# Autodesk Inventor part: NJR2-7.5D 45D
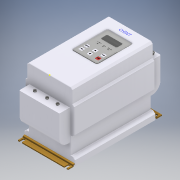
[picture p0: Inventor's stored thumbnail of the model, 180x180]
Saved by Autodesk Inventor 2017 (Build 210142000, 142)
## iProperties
Part Number: NJR2-7.5D 45D
Material: Типовые
Document SubType Name: Modeling
Designer: RSagdiev
Density: 1 g/cm^3
Appearance: По умолчанию
Author: RSagdiev
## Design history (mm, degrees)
sketch "Эскиз1"
  geometry: L1 (0, 0)-(14.471, 0) reference; L2 (0, 0)-(0, 21.118) reference; L3 (0, 0)-(230, 0); L4 (230, 0)-(230, 20); L5 (230, 190)-(0, 190); L6 (0, 190)-(0, 150); L7 (230, 20)-(0, 20); L8 (230, 70)-(0, 70); L9 (230, 70)-(230, 150); L10 (230, 20)-(230, 70); L11 (0, 70)-(0, 20); L12 (0, 20)-(0, 0); L13 (230, 150)-(0, 150); L14 (230, 150)-(230, 190); L15 (0, 150)-(0, 70)
  constraints: 30 end point, 17 parallel, 14 perpendicular, 3 horizontal, 2 vertical, 1 point on line
  dimensions: "d0" = 230 distance of L5.end L5.start; "d1" = 190 distance of L5.start L3.end; "d2" = 20 distance between parallel lines of L3 L7; "d3" = 50 distance between parallel lines of L8 L7; "d4" = 80 distance between parallel lines of L13 L8
extrude "Выдавливание1" new body sketch "Эскиз1" stored distance "d5" = 145; taper "d6" = 0 deg
extrude "Выдавливание2" join sketch "Эскиз1" stored distance "d7" = 120; taper "d8" = 0 deg
extrude "Выдавливание3" join sketch "Эскиз1" stored distance "d9" = 140; taper "d10" = 0 deg
extrude "Выдавливание4" join sketch "Эскиз1" stored distance "d11" = 130; taper "d12" = 0 deg
chamfer "Фаска1" distance "d13" = 5; stored, may be unused: second distance "d14" = 2, angle "d15" = 45 deg
sketch "Эскиз2"
  geometry: L1 (249, 0)-(234, 0); L2 (233, 1)-(233, 3); L3 (232, 4)-(-2, 4); L4 (-3, 3)-(-3, 1); L5 (-4, 0)-(-19, 0); L6 (230, 15)-(230, 0) reference; L7 (230, 0)-(0, 0) reference; L8 (0, 0)-(0, 15) reference; L9 (249, 3)-(236, 3); L10 (232, 7)-(-2, 7); L11 (-6, 3)-(-19, 3); L12 (-19, 0)-(-19, 3); L13 (249, 3)-(249, 0); A1 r 1 centre (-4, 1) between (-4, 0) and (-3, 1); A2 r 1 centre (-2, 3) between (-2, 4) and (-3, 3); A3 r 1 centre (234, 1) between (233, 1) and (234, 0); A4 r 1 centre (232, 3) between (233, 3) and (232, 4); A5 r 4 centre (232, 3) between (236, 3) and (232, 7); A6 r 4 centre (-2, 3) between (-2, 7) and (-6, 3); 6 further points
  constraints: 20 end point, 12 point on circle, 10 point on line, 8 tangent, 6 centre point, 4 perpendicular, 3 equal radius, 1 horizontal, 1 parallel, 4 other
  dimensions: "d16" = 4 distance of point (233, 0) point (233, 4); "d17" = 3 distance between parallel lines of L2 L6; "d18" = 4 distance between parallel lines of L7 L3; "d19" = 16 distance of point (233, 0) L1.start; "d20" = 16 distance of point (-3, 0) L5.end (= d19); "d21" = 4 distance of point (-3, 4) point (-3, 0) (derived); "d22" = 3 distance between parallel lines of L4 L8 (= d17); "d23" = 268 distance of L5.end L1.start (derived); "d24" = 1 radius of A1; "d25" = 3 distance between parallel lines of L1 L9
extrude "Выдавливание5" new body sketch "Эскиз2" stored distance "d26" = 143; taper "d27" = 0 deg
sketch "Эскиз4"
  geometry: L1 (260, 138)-(-30, 138); L2 (-30, 138)-(-30, 50); L3 (-30, 50)-(260, 50); L4 (260, 50)-(260, 138); L5 (0, 70)-(230, 70) reference; L6 (230, 190)-(230, 150) reference; L7 (230, 0)-(0, 0) reference; L8 (0, 150)-(230, 150) reference
  constraints: 8 end point, 2 parallel, 1 horizontal, 1 perpendicular
  dimensions: "d28" = 290 distance between parallel lines of L2 L4; "d187" = 20 distance between parallel lines of L5 L3; "d188" = 30 distance between parallel lines of L6 L4; "d189" = 50 distance between parallel lines of L7 L3 (derived); "d190" = 12 distance between parallel lines of L8 L1
extrude "Выдавливание6" join sketch "Эскиз4" stored distance "d32" = 115; taper "d33" = 0 deg
fillet "Сопряжение1" dims "d35" = 25
sketch "Эскиз5" dims "d44" = 10
  geometry: L1 (115, 0)-(0, 0) reference; L2 (115, 30)-(115, 0) reference; L3 (115, 30)-(0, 30) reference; L4 (0, 0)-(0, 30) reference; L5 (0, -260)-(115, -260) reference; L6 (0, -230)-(115, -230) reference; L7 (0, -260)-(0, -230) reference; L8 (115, -230)-(115, -260) reference; C1 r 4 at (20, 20); C2 r 4 at (35.833, 20); C3 r 4 at (51.667, 20); C4 r 4 at (67.5, 20); C5 r 4 at (83.333, 20); C6 r 4 at (99.167, 20); 1 further point
  constraints: 6 centre point, 1 horizontal, 10 other
  dimensions: "d36" = 8 diameter of C1; "d37" = 115 distance between parallel lines of L2 L4 (derived); "d38" = 20 distance from line of C1.centre L4; "d41" = 15.83333 distance of C1.centre C2.centre (= -0.166667 x d38 + 0.166667 x d37)
  node "Спроецированная петля1"
extrude "Выдавливание7" cut sketch "Эскиз5" distance "d46" = 20; taper "d47" = 0 deg
extrude "Выдавливание8" new body sketch "Эскиз5" distance "d48" = 20; taper "d49" = 0 deg
sketch "Эскиз6" dims "d50" = 12, "d56" = 10
  geometry: L1 (0, 6)-(5.196, 3); L2 (5.196, 3)-(5.196, -3); L3 (5.196, -3)-(0, -6); L4 (0, -6)-(-5.196, -3); L5 (-5.196, -3)-(-5.196, 3); L6 (-5.196, 3)-(0, 6); L7 (95, 10)-(-20, 10) reference; L8 (15.833, 6)-(21.029, 3); L9 (21.029, 3)-(21.029, -3); L10 (21.029, -3)-(15.833, -6); L11 (15.833, -6)-(10.637, -3); L12 (10.637, -3)-(10.637, 3); L13 (10.637, 3)-(15.833, 6); L14 (31.667, 6)-(36.863, 3); L15 (36.863, 3)-(36.863, -3); L16 (36.863, -3)-(31.667, -6); L17 (31.667, -6)-(26.471, -3); L18 (26.471, -3)-(26.471, 3); L19 (26.471, 3)-(31.667, 6); L20 (47.5, 6)-(52.696, 3); L21 (52.696, 3)-(52.696, -3); L22 (52.696, -3)-(47.5, -6); L23 (47.5, -6)-(42.304, -3); L24 (42.304, -3)-(42.304, 3); L25 (42.304, 3)-(47.5, 6); L26 (63.333, 6)-(68.529, 3); L27 (68.529, 3)-(68.529, -3); L28 (68.529, -3)-(63.333, -6); L29 (63.333, -6)-(58.137, -3); L30 (58.137, -3)-(58.137, 3); L31 (58.137, 3)-(63.333, 6); L32 (79.167, 6)-(84.363, 3); L33 (84.363, 3)-(84.363, -3); L34 (84.363, -3)-(79.167, -6); L35 (79.167, -6)-(73.971, -3); L36 (73.971, -3)-(73.971, 3); L37 (73.971, 3)-(79.167, 6); 13 further points
  constraints: 72 end point, 6 coincident, 6 horizontal, 6 vertical alignment, 95 other
  dimensions: "d53" = 15.83333 distance of point (0, 0) point (15.833, 0) (= -0.166667 x d38 + 0.166667 x d37)
extrude "Выдавливание9" join sketch "Эскиз6" distance "d58" = 5; taper "d59" = 0 deg
sketch "Эскиз7" dims "d185" = 10
  geometry: L1 (2.964, 2.686)-(3.808, -1.224); L2 (3.808, -1.224)-(0.844, -3.91); L3 (0.844, -3.91)-(-2.964, -2.686); L4 (-2.964, -2.686)-(-3.808, 1.224); L5 (-3.808, 1.224)-(-0.844, 3.91); L6 (-0.844, 3.91)-(2.964, 2.686); L7 (95, 10)-(-20, 10) reference; L8 (18.764, 2.686)-(19.608, -1.224); L9 (19.608, -1.224)-(16.644, -3.91); L10 (16.644, -3.91)-(12.836, -2.686); L11 (12.836, -2.686)-(11.992, 1.224); L12 (11.992, 1.224)-(14.956, 3.91); L13 (14.956, 3.91)-(18.764, 2.686); L14 (34.564, 2.686)-(35.408, -1.224); L15 (35.408, -1.224)-(32.444, -3.91); L16 (32.444, -3.91)-(28.636, -2.686); L17 (28.636, -2.686)-(27.792, 1.224); L18 (27.792, 1.224)-(30.756, 3.91); L19 (30.756, 3.91)-(34.564, 2.686); L20 (50.364, 2.686)-(51.208, -1.224); L21 (51.208, -1.224)-(48.244, -3.91); L22 (48.244, -3.91)-(44.436, -2.686); L23 (44.436, -2.686)-(43.592, 1.224); L24 (43.592, 1.224)-(46.556, 3.91); L25 (46.556, 3.91)-(50.364, 2.686); L26 (66.164, 2.686)-(67.008, -1.224); L27 (67.008, -1.224)-(64.044, -3.91); L28 (64.044, -3.91)-(60.236, -2.686); L29 (60.236, -2.686)-(59.392, 1.224); L30 (59.392, 1.224)-(62.356, 3.91); L31 (62.356, 3.91)-(66.164, 2.686); L32 (81.964, 2.686)-(82.808, -1.224); L33 (82.808, -1.224)-(79.844, -3.91); L34 (79.844, -3.91)-(76.036, -2.686); L35 (76.036, -2.686)-(75.192, 1.224); L36 (75.192, 1.224)-(78.156, 3.91); L37 (78.156, 3.91)-(81.964, 2.686); C1 r 6 at (0, 0) reference; A1 r 4 centre (0, 0) between (2.964, 2.686) and (-2.964, -2.686); A2 r 4 centre (15.8, 0) between (18.764, 2.686) and (12.836, -2.686); A3 r 4 centre (31.6, 0) between (34.564, 2.686) and (28.636, -2.686); A4 r 4 centre (47.4, 0) between (50.364, 2.686) and (44.436, -2.686); A5 r 4 centre (63.2, 0) between (66.164, 2.686) and (60.236, -2.686); A6 r 4 centre (79, 0) between (81.964, 2.686) and (76.036, -2.686); 1 further point
  constraints: 72 end point, 36 point on circle, 6 centre point, 5 equal length, 1 horizontal, 70 other
  dimensions: "d179" = 2 radial gap between concentric circles of C1 A1; "d182" = 15.8 distance of L1.start L8.start
extrude "Выдавливание10" cut sketch "Эскиз7" distance "d66" = 1.5; taper "d67" = 0 deg
fillet "Сопряжение2" dims "d68" = 2
sketch "Эскиз8"
  geometry: L1 (0, -268)-(143, -268) reference; L2 (143, 0)-(0, 0) reference; L3 (143, 0)-(143, -15) reference; L4 (0, -15)-(0, 0) reference; L5 (7.5, -9)-(7.5, -14); L6 (135.5, -9)-(135.5, -14); L7 (7.5, -9)-(135.5, -9); L8 (7.5, -259)-(7.5, -268); L9 (4, -259)-(4, -268); L10 (11, -268)-(11, -259); L11 (7.5, -9)-(7.5, -259); L12 (7.5, -259)-(135.5, -259); L13 (135.5, -9)-(135.5, -259); L14 (135.5, -259)-(135.5, -268); L15 (132, -259)-(132, -268); L16 (139, -268)-(139, -259); A1 r 3.5 centre (7.5, -9) between (10.779, -10.225) and (4.221, -10.225); A2 r 5 centre (7.5, -14) between (4.221, -10.225) and (10.779, -10.225); A3 r 3.5 centre (135.5, -9) between (138.779, -10.225) and (132.221, -10.225); A4 r 5 centre (135.5, -14) between (132.221, -10.225) and (138.779, -10.225); A5 r 3.5 centre (7.5, -259) between (11, -259) and (4, -259); A6 r 3.5 centre (7.5, -268) between (4, -268) and (11, -268); A7 r 3.5 centre (135.5, -259) between (139, -259) and (132, -259); A8 r 3.5 centre (135.5, -268) between (132, -268) and (139, -268); 5 further points
  constraints: 28 end point, 16 point on circle, 8 centre point, 8 tangent, 4 vertical, 3 coincident, 2 horizontal, 2 midpoint, 2 parallel, 2 perpendicular, 2 point on line
  dimensions: "d69" = 128 distance of point (135.5, -9) point (7.5, -9); "d70" = 250 distance of L8.start point (7.5, -9); "d71" = 268 distance between parallel lines of L1 L2 (derived); "d72" = 9 distance from line of L2 point (7.5, -9) (= -0.5 x d70 + 0.5 x d71); "d73" = 143 distance between parallel lines of L3 L4 (derived); "d74" = 7.5 distance from line of L4 point (7.5, -9) (= -0.5 x d69 + 0.5 x d73); "d75" = 7 diameter of A1; "d76" = 10 diameter of A2; "d77" = 5 distance of L5.start L5.end; "d78" = 7 diameter of A3; "d79" = 10 diameter of A4; "d80" = 5 distance of L6.start L6.end; "d81" = 7 diameter of A6; "d82" = 7 diameter of A8
extrude "Выдавливание11" cut sketch "Эскиз8" distance "d83" = 5.5; taper "d84" = 0 deg
fillet "Сопряжение3" dims "d85" = 2
sketch "Эскиз9"
  geometry: L1 (125, 0)-(5, 0); L2 (5, 226)-(125, 226); L3 (33, 193)-(97, 193); L4 (100, 190)-(100, 96); L5 (97, 93)-(33, 93); L6 (30, 96)-(30, 190); L7 (97, 195)-(33, 195); L8 (28, 190)-(28, 96); L9 (33, 91)-(97, 91); L10 (102, 96)-(102, 190); L11 (125, 226)-(125, 0); L12 (5, 0)-(5, 226); A1 r 3 centre (33, 190) between (33, 193) and (30, 190); A2 r 3 centre (97, 190) between (100, 190) and (97, 193); A3 r 3 centre (97, 96) between (97, 93) and (100, 96); A4 r 3 centre (33, 96) between (30, 96) and (33, 93); A5 r 5 centre (33, 190) between (33, 195) and (28, 190); A6 r 5 centre (33, 96) between (28, 96) and (33, 91); A7 r 5 centre (97, 96) between (97, 91) and (102, 96); A8 r 5 centre (97, 190) between (102, 190) and (97, 195); 4 further points
  constraints: 24 end point, 16 point on circle, 8 centre point, 8 tangent, 6 point on line, 4 parallel, 3 equal radius, 2 perpendicular, 1 horizontal, 7 other
  dimensions: "d86" = 70 distance of point (100, 93) point (30, 93); "d87" = 100 distance of point (100, 193) point (100, 93); "d90" = 33 distance between parallel lines of L2 L3 (computed from d89, d87); "d92" = 3 radius of A1; "d93" = 2 distance between parallel lines of L3 L7
extrude "Выдавливание12" cut sketch "Эскиз9" distance "d94" = 25; taper "d95" = 0 deg
extrude "Выдавливание13" new body sketch "Эскиз9" distance "d96" = 25; taper "d97" = 0 deg
sketch "Эскиз10"
  geometry: L1 (30, 190)-(30, 150.574); L2 (33, 93)-(97, 93); L3 (100, 96)-(100, 150.574); L4 (97, 193)-(33, 193); L5 (97, 193)-(33, 193) reference; L6 (30, 190)-(30, 96) reference; L7 (30, 150.574)-(30, 96); L8 (100, 150.574)-(100, 190); L9 (45.628, 161.287)-(84.628, 161.287); L10 (87.628, 164.287)-(87.628, 176.287); L11 (84.628, 179.287)-(45.628, 179.287); L12 (42.628, 176.287)-(42.628, 164.287); L13 (42.628, 161.287)-(87.628, 179.287); L14 (87.628, 161.287)-(42.628, 179.287); A1 r 3 centre (33, 96) between (30, 96) and (33, 93); A2 r 3 centre (97, 96) between (97, 93) and (100, 96); A3 r 3 centre (97, 190) between (100, 190) and (97, 193); A4 r 3 centre (33, 190) between (33, 193) and (30, 190); A5 r 55 centre (65, 193) between (30, 150.574) and (100.197, 150.737); A6 r 3 centre (45.628, 176.287) between (45.628, 179.287) and (42.628, 176.287); A7 r 3 centre (45.628, 164.287) between (42.628, 164.287) and (45.628, 161.287); A8 r 3 centre (84.628, 176.287) between (87.628, 176.287) and (84.628, 179.287); A9 r 3 centre (84.628, 164.287) between (84.628, 161.287) and (87.628, 164.287); 2 further points
  constraints: 20 end point, 11 point on circle, 9 centre point, 9 point on line, 8 tangent, 3 equal radius, 3 midpoint, 2 parallel, 1 horizontal, 1 perpendicular
  dimensions: "d98" = 55 radius of A5; "d99" = 45 distance of L14.end L13.end; "d100" = 18 distance of L13.end L14.start; "d101" = 22.7132 distance from line of L4 point (65.128, 170.287); "d102" = 35.1281 distance from line of L1 point (65.128, 170.287); "d103" = 3 radius of A6 (derived)
extrude "Выдавливание14" cut sketch "Эскиз10" distance "d104" = 1; taper "d105" = 0 deg
sketch "Эскиз11"
  geometry: L1 (30, 150.574)-(30, 96) reference; L2 (33, 93)-(97, 93) reference; L3 (100, 96)-(100, 150.574) reference; L4 (30, 150.574)-(30, 96) reference; L5 (30, 123)-(100, 123); L6 (100, 96)-(100, 150.574) reference; L7 (30, 108)-(100, 108); L8 (33, 93)-(97, 93) reference; L9 (41.667, 93)-(41.667, 143.195); L10 (88.333, 93)-(88.333, 143.195); L11 (65, 93)-(65, 138); L12 (36.667, 128)-(46.667, 128); L13 (46.667, 128)-(46.667, 118); L14 (46.667, 118)-(36.667, 118); L15 (36.667, 118)-(36.667, 128); L16 (36.667, 128)-(46.667, 118); L17 (46.667, 128)-(36.667, 118); L18 (36.667, 113)-(46.667, 113); L19 (46.667, 113)-(46.667, 103); L20 (46.667, 103)-(36.667, 103); L21 (36.667, 103)-(36.667, 113); L22 (36.667, 113)-(46.667, 103); L23 (46.667, 113)-(36.667, 103); L24 (60, 128)-(70, 128); L25 (70, 128)-(70, 118); L26 (70, 118)-(60, 118); L27 (60, 118)-(60, 128); L28 (60, 128)-(70, 118); L29 (70, 128)-(60, 118); L30 (60, 113)-(70, 113); L31 (70, 113)-(70, 103); L32 (70, 103)-(60, 103); L33 (60, 103)-(60, 113); L34 (60, 113)-(70, 103); L35 (70, 113)-(60, 103); L36 (83.333, 128)-(93.333, 128); L37 (93.333, 128)-(93.333, 118); L38 (93.333, 118)-(83.333, 118); L39 (83.333, 118)-(83.333, 128); L40 (83.333, 128)-(93.333, 118); L41 (93.333, 128)-(83.333, 118); L42 (83.333, 113)-(93.333, 113); L43 (93.333, 113)-(93.333, 103); L44 (93.333, 103)-(83.333, 103); L45 (83.333, 103)-(83.333, 113); L46 (83.333, 113)-(93.333, 103); L47 (93.333, 113)-(83.333, 103); L48 (46.767, 128.1)-(36.567, 128.1); L49 (36.567, 128.1)-(36.567, 117.9); L50 (36.567, 117.9)-(46.767, 117.9); L51 (46.767, 117.9)-(46.767, 128.1); L52 (70.1, 128.1)-(59.9, 128.1); L53 (59.9, 128.1)-(59.9, 117.9); L54 (59.9, 117.9)-(70.1, 117.9); L55 (70.1, 117.9)-(70.1, 128.1); L56 (93.433, 128.1)-(83.233, 128.1); L57 (83.233, 128.1)-(83.233, 117.9); L58 (83.233, 117.9)-(93.433, 117.9); L59 (93.433, 117.9)-(93.433, 128.1); L60 (46.767, 113.1)-(36.567, 113.1); L61 (36.567, 113.1)-(36.567, 102.9); L62 (36.567, 102.9)-(46.767, 102.9); L63 (46.767, 102.9)-(46.767, 113.1); L64 (70.1, 113.1)-(59.9, 113.1)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; A1 r 55 centre (65, 193) between (30, 150.574) and (100, 150.574) reference; A2 r 3 centre (33, 96) between (30, 96) and (33, 93) reference; A3 r 3 centre (97, 96) between (97, 93) and (100, 96) reference; A4 r 55 centre (65, 193) between (30, 150.574) and (100, 150.574) reference; 8 further points
  constraints: 130 end point, 24 parallel, 16 midpoint, 16 point on line, 14 perpendicular, 7 horizontal, 4 point on circle, 1 vertical, 18 other
  dimensions: "d106" = 70 distance between parallel lines of L3 L1 (derived); "d107" = 45 distance from line of L2 L11.end (derived); "d108" = 15 distance between parallel lines of L7 L5 (= 0.333333 x d107); "d109" = 15 distance from line of L11.end L5 (= 0.333333 x d107); "d110" = 23.33333 distance between parallel lines of L11 L10 (= 0.333333 x d106); "d111" = 23.33333 distance between parallel lines of L11 L9 (= d110); "d112" = 10 distance of L13.end L14.end; "d113" = 10 distance of L12.end L13.end; "d114" = 10 distance of L19.end L20.end; "d115" = 10 distance of L18.end L19.end; "d116" = 10 distance of L25.end L26.end; "d117" = 10 distance of L24.end L25.end; "d118" = 10 distance of L31.end L32.end; "d119" = 10 distance of L30.end L31.end; "d120" = 10 distance of L37.end L38.end; "d121" = 10 distance of L36.end L37.end; "d122" = 10 distance of L43.end L44.end; "d123" = 10 distance of L42.end L43.end; "d124" = 0.1 distance between parallel lines of L12 L48; "d125" = 0.1 distance between parallel lines of L24 L52; "d126" = 0.1 distance between parallel lines of L36 L56; "d127" = 0.1 distance between parallel lines of L18 L60; "d128" = 0.1 distance between parallel lines of L30 L64; "d129" = 0.1 distance between parallel lines of L42 L68
extrude "Выдавливание15" cut sketch "Эскиз11" distance "d130" = 3; taper "d131" = 0 deg
sketch "Эскиз12"
  geometry: L1 (100, 96)-(100, 150.574) reference; L2 (50, 144.701)-(80, 144.701); C1 r 1.5 at (65, 144.701); C2 r 1.5 at (80, 144.701); C3 r 1.5 at (50, 144.701); C4 r 1.6 at (50, 144.701); C5 r 1.6 at (65, 144.701); C6 r 1.6 at (80, 144.701); A1 r 55 centre (65, 193) between (30, 150.574) and (100, 150.574) reference; 1 further point
  constraints: 6 centre point, 2 end point, 1 coincident, 1 horizontal, 1 midpoint
  dimensions: "d132" = 3 diameter of C1; "d133" = 3 diameter of C2; "d134" = 3 diameter of C3; "d135" = 48.29941 distance of A1.centre C1.centre; "d136" = 35 distance from line of L1 C1.centre; "d137" = 15 distance of C1.centre C2.centre; "d138" = 15 distance of C1.centre L2.start; "d139" = 0.1 radial gap between concentric circles of C3 C4; "d140" = 0.1 radial gap between concentric circles of C1 C5; "d141" = 0.1 radial gap between concentric circles of C2 C6
extrude "Выдавливание16" cut sketch "Эскиз12" distance "d142" = 3; taper "d143" = 0 deg
sketch "Эскиз13"
  geometry: L1 (45, 150.348)-(102.075, 150.348); L2 (102.075, 150.348)-(102.075, 146.701); L3 (102.075, 146.701)-(45, 146.701); L4 (45, 146.701)-(45, 150.348); C1 r 1.5 at (50, 144.701) reference; 1 further point
  constraints: 2 other
  dimensions: "d144" = 2 vertical distance of L3.end C1.centre; "d145" = 5 horizontal distance of C1.centre L3.end
feature "Рельеф1" sketch "Эскиз13" dims "d10" = 0, "d146" = 0.1, "d147" = 0
sketch "Эскиз14"
  geometry: L1 (36.734, 124.406)-(51.145, 124.406); L2 (51.145, 124.406)-(51.145, 120.906); L3 (51.145, 120.906)-(36.734, 120.906); L4 (36.734, 120.906)-(36.734, 124.406); L5 (38.873, 106.059)-(38.873, 109.559); L6 (38.873, 109.559)-(53.285, 109.559); L7 (53.285, 109.559)-(53.285, 106.059); L8 (53.285, 106.059)-(38.873, 106.059); L9 (84.699, 105.985)-(84.699, 109.485); L10 (84.699, 109.485)-(99.11, 109.485); L11 (99.11, 109.485)-(99.11, 105.985); L12 (99.11, 105.985)-(84.699, 105.985); L13 (85.21, 120.906)-(85.21, 124.406); L14 (85.21, 124.406)-(99.621, 124.406); L15 (99.621, 124.406)-(99.621, 120.906); L16 (99.621, 120.906)-(85.21, 120.906); 1 further point
  constraints: 8 other
feature "Рельеф2" dims "d10" = 0, "d148" = 0.1, "d149" = 0
feature "Рельеф3" dims "d10" = 0, "d150" = 0.1, "d151" = 0
feature "Рельеф4" dims "d10" = 0, "d152" = 0.1, "d153" = 0
feature "Рельеф5" dims "d10" = 0, "d154" = 0.1, "d155" = 0
sketch "Эскиз15" dims "d156" = 6, "d157" = 6
  geometry: L1 (60, 128)-(60, 118) reference; L2 (60, 118)-(70, 118) reference; L3 (70, 118)-(70, 128) reference; L4 (70, 128)-(60, 128) reference; L5 (60, 113)-(60, 103) reference; L6 (60, 103)-(70, 103) reference; L7 (70, 103)-(70, 113) reference; L8 (70, 113)-(60, 113) reference; L9 (60, 118)-(70, 128); L10 (60, 128)-(70, 118); L11 (60, 113)-(70, 103); L12 (70.1, 113.1)-(70.1, 102.9) reference; L13 (70.1, 113.1)-(60, 103); L14 (65.05, 126)-(67.573, 121.457); L15 (67.573, 121.457)-(62.377, 121.544); L16 (62.377, 121.544)-(65.05, 126); L17 (65.05, 105.05)-(62.452, 109.55); L18 (62.452, 109.55)-(67.648, 109.55); L19 (67.648, 109.55)-(65.05, 105.05); 5 further points
  constraints: 20 end point, 2 coincident, 2 midpoint, 2 perpendicular, 1 parallel, 1 vertical alignment, 19 other
  node "Спроецированная петля11"
  node "Спроецированная петля12"
feature "Рельеф6" dims "d10" = 0, "d158" = 0.1, "d159" = 0
feature "Рельеф7" dims "d10" = 0, "d160" = 0.1, "d161" = 0
sketch "Эскиз16"
  geometry: L1 (2, -30)-(113, -30) reference; L2 (0, 0)-(115, 0) reference; L3 (90, -10)-(0, -10); L4 (0, -28)-(0, -5) reference; L5 (113, 260)-(2, 260) reference; L6 (115, 230)-(0, 230) reference; L7 (115, 0)-(115, -28) reference; L8 (0, -28)-(0, 0) reference; L9 (0, 230)-(0, 258) reference; L10 (115, 258)-(115, 230) reference; C1 r 4 at (25, -10); C2 r 4 at (60, -10); C3 r 4 at (90, -10); A1 r 2 centre (2, -28) between (0, -28) and (2, -30) reference; A2 r 2 centre (113, -28) between (113, -30) and (115, -28) reference; A3 r 2 centre (113, 258) between (115, 258) and (113, 260) reference; A4 r 2 centre (2, 258) between (2, 260) and (0, 258) reference; 1 further point
  constraints: 3 centre point, 3 point on line, 2 end point, 1 horizontal
  dimensions: "d162" = 8 diameter of C1; "d163" = 8 diameter of C2; "d164" = 8 diameter of C3; "d166" = 20 distance from line of L3.start L1; "d167" = 30 distance of C2.centre L3.start; "d168" = 35 distance of C1.centre C2.centre; "d191" = 25 distance from line of L8 C1.centre
extrude "Выдавливание17" new body sketch "Эскиз16" distance "d169" = 3; taper "d170" = 0 deg
sketch "Эскиз17"
  geometry: L1 (-23, -20)-(88, -20) reference; L2 (-25, 10)-(90, 10) reference; L3 (0, 3)-(2.598, 1.5); L4 (2.598, 1.5)-(2.598, -1.5); L5 (2.598, -1.5)-(0, -3); L6 (0, -3)-(-2.598, -1.5); L7 (-2.598, -1.5)-(-2.598, 1.5); L8 (-2.598, 1.5)-(0, 3); L9 (35, 3)-(37.598, 1.5); L10 (37.598, 1.5)-(37.598, -1.5); L11 (37.598, -1.5)-(35, -3); L12 (35, -3)-(32.402, -1.5); L13 (32.402, -1.5)-(32.402, 1.5); L14 (32.402, 1.5)-(35, 3); L15 (65, 3)-(67.598, 1.5); L16 (67.598, 1.5)-(67.598, -1.5); L17 (67.598, -1.5)-(65, -3); L18 (65, -3)-(62.402, -1.5); L19 (62.402, -1.5)-(62.402, 1.5); L20 (62.402, 1.5)-(65, 3); L21 (88, 270)-(-23, 270) reference; L22 (90, 240)-(-25, 240) reference; L23 (90, 10)-(90, -18) reference; L24 (-25, -18)-(-25, 10) reference; L25 (-25, 240)-(-25, 268) reference; L26 (90, 268)-(90, 240) reference; C1 r 4 at (0, 0) reference; C2 r 4 at (35, 0) reference; C3 r 4 at (65, 0) reference; C4 r 4 at (35, 0) reference; A1 r 2 centre (-23, -18) between (-25, -18) and (-23, -20) reference; A2 r 2 centre (88, -18) between (88, -20) and (90, -18) reference; A3 r 2 centre (88, 268) between (90, 268) and (88, 270) reference; A4 r 2 centre (-23, 268) between (-23, 270) and (-25, 268) reference; 4 further points
  constraints: 36 end point, 3 coincident, 3 vertical alignment, 45 other
  dimensions: "d171" = 1 dimension on C1; "d172" = 1 dimension on C2; "d173" = 1 dimension on C3
extrude "Выдавливание18" cut sketch "Эскиз17" distance "d174" = 0.5; taper "d175" = 0 deg
fillet "Сопряжение4" dims "d176" = 1
sketch "Эскиз18"
  geometry: L1 (46.683, 214.728)-(62.561, 214.728); L2 (62.561, 214.728)-(62.561, 211.091); L3 (62.561, 211.091)-(46.683, 211.091); L4 (46.683, 211.091)-(46.683, 214.728); 1 further point
  constraints: 2 other
feature "Рельеф8" sketch "Эскиз18" dims "d10" = 0, "d177" = 0.1, "d178" = 0
node "Твердое тело1"
node "Твердое тело2"
node "Твердое тело3"
node "Твердое тело4"
node "Спроецированная петля10"
node "Спроецированная петля13"
node "Твердое тело5"
node "Спроецированная петля14"
node "Спроецированная петля15"
node "Спроецированная петля16"
node "Спроецированная петля17"
other parameters: "d89" = 226 (derived)
